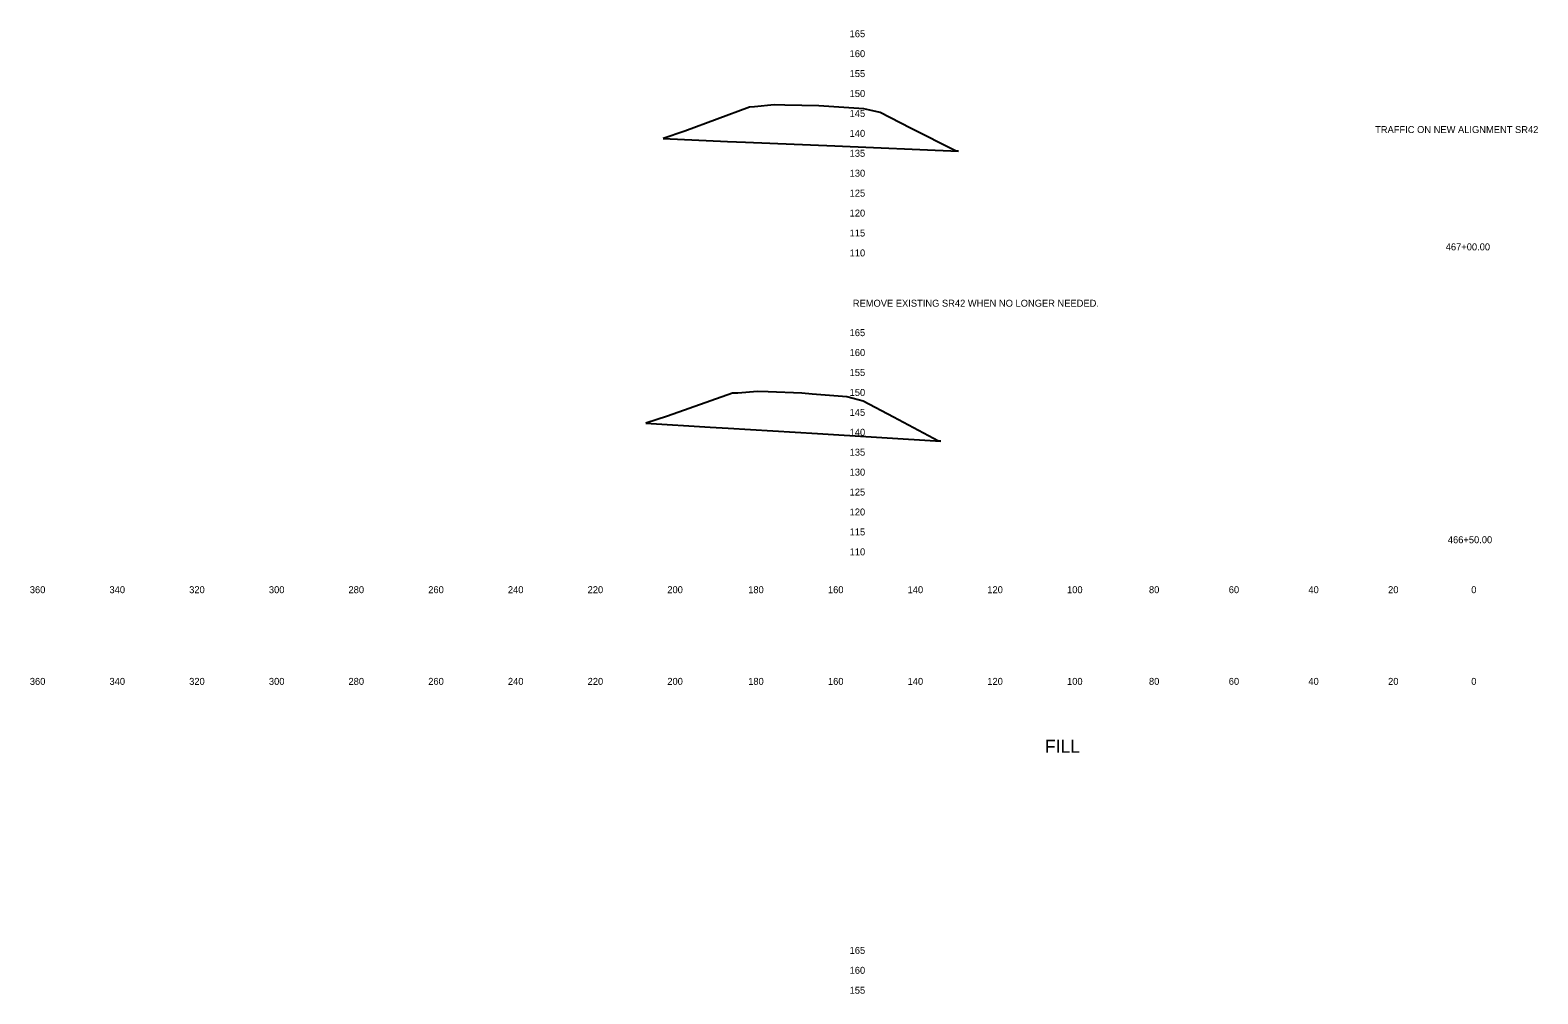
# Model space of a CAD drawing. Extents: x 21281 to 22024, y 6472 to 15208.
# Drawn here: x 21280.5 to 21658.8, y 8904.8 to 9146.6 of the extents above; entities that cross this region are included whole.
import ezdxf

# ---------------------------------------------------------------- set-up
doc = ezdxf.new("R2010")
doc.units = 0
for name, color, linetype in [('XS_SHEET_LABELS_ELEVATION', 7, 'Continuous'), ('XS_SHEET_LABELS_OFFSET', 7, 'Continuous'), ('XS_SHEET_LABELS_STATION', 7, 'Continuous'), ('XS_X_EXCESS', 7, 'Continuous')]:
    doc.layers.add(name, color=color, linetype=linetype)

msp = doc.modelspace()

# ---------------------------------------------------------------- linework, layer by layer
at = {"layer": 'XS_X_EXCESS'}
for p, q in [((21513.48, 9116.21), (21512.91, 9116.27)), ((21509.05, 9043.45), (21508.48, 9043.52))]:
    msp.add_line(p, q, dxfattribs=at)
for points in [[(21512.91, 9116.27), (21501.45, 9122.04), (21493.79, 9125.91), (21491.23, 9126.52), (21489.71, 9126.91), (21480.95, 9127.48), (21478.39, 9127.66), (21469.88, 9127.81), (21467.25, 9127.86), (21462.29, 9127.38), (21460.99, 9127.32), (21444.79, 9121.29), (21439.37, 9119.4)], [(21439.37, 9119.4), (21455.53, 9118.71), (21460.02, 9118.52), (21482.44, 9117.56), (21513.48, 9116.21)], [(21508.48, 9043.52), (21497.13, 9049.5), (21489.54, 9053.5), (21486.99, 9054.16), (21485.48, 9054.58), (21476.74, 9055.31), (21474.18, 9055.54), (21465.67, 9055.84), (21463.04, 9055.94), (21458.08, 9055.55), (21456.77, 9055.52), (21440.47, 9049.79), (21435.01, 9048)], [(21435.01, 9048), (21451.16, 9047.01), (21455.65, 9046.73), (21478.04, 9045.37), (21509.05, 9043.45)]]:
    msp.add_lwpolyline(points, dxfattribs=at)

# ---------------------------------------------------------------- texts
at = {"layer": 'XS_SHEET_LABELS_ELEVATION'}
for s, p in [('  165  ', (21484.84, 9144.84)), ('  160  ', (21484.84, 9139.84)), ('  155  ', (21484.84, 9134.84)), ('  150  ', (21484.84, 9129.84)), ('  145  ', (21484.84, 9124.84)), ('  140  ', (21484.84, 9119.84)), ('  135  ', (21484.84, 9114.84)), ('  130  ', (21484.84, 9109.84)), ('  125  ', (21484.84, 9104.84)), ('  120  ', (21484.84, 9099.84)), ('  115  ', (21484.84, 9094.84)), ('  110  ', (21484.84, 9089.84)), ('  165  ', (21484.84, 9069.84)), ('  160  ', (21484.84, 9064.84)), ('  155  ', (21484.84, 9059.84)), ('  150  ', (21484.84, 9054.84)), ('  145  ', (21484.84, 9049.84)), ('  140  ', (21484.84, 9044.84)), ('  135  ', (21484.84, 9039.84)), ('  130  ', (21484.84, 9034.84)), ('  125  ', (21484.84, 9029.84)), ('  120  ', (21484.84, 9024.84)), ('  115  ', (21484.84, 9019.84)), ('  110  ', (21484.84, 9014.84)), ('  165  ', (21484.84, 8914.84)), ('  160  ', (21484.84, 8909.84)), ('  155  ', (21484.84, 8904.84))]:
    msp.add_text(s, height=1.75, dxfattribs=at).set_placement(p)
at = {"layer": 'XS_SHEET_LABELS_OFFSET'}
for s, height, p in [('  360  ', 1.75, (21279.14, 9005.34)), ('  340  ', 1.75, (21299.13, 9005.34)), ('  320  ', 1.75, (21319.13, 9005.34)), ('  300  ', 1.75, (21339.13, 9005.34)), ('  280  ', 1.75, (21359.1, 9005.34)), ('  260  ', 1.75, (21379.11, 9005.34)), ('  240  ', 1.75, (21399.1, 9005.34)), ('  220  ', 1.75, (21419.1, 9005.34)), ('  200  ', 1.75, (21439.1, 9005.34)), ('  180  ', 1.75, (21459.39, 9005.34)), ('  160  ', 1.75, (21479.4, 9005.34)), ('  140  ', 1.75, (21499.39, 9005.34)), ('  120  ', 1.75, (21519.39, 9005.34)), ('  100  ', 1.75, (21539.39, 9005.34)), ('  80  ', 1.75, (21559.95, 9005.34)), ('  60  ', 1.75, (21579.97, 9005.34)), ('  40  ', 1.75, (21599.95, 9005.34)), ('  20  ', 1.75, (21619.95, 9005.34)), ('  0  ', 1.75, (21640.81, 9005.34)), ('  0  ', 1.75, (21640.81, 9005.34)), ('  360  ', 1.75, (21279.14, 8982.34)), ('  340  ', 1.75, (21299.13, 8982.34)), ('  320  ', 1.75, (21319.13, 8982.34)), ('  300  ', 1.75, (21339.13, 8982.34)), ('  280  ', 1.75, (21359.1, 8982.34)), ('  260  ', 1.75, (21379.11, 8982.34)), ('  240  ', 1.75, (21399.1, 8982.34)), ('  220  ', 1.75, (21419.1, 8982.34)), ('  200  ', 1.75, (21439.1, 8982.34)), ('  180  ', 1.75, (21459.39, 8982.34)), ('  160  ', 1.75, (21479.4, 8982.34)), ('  140  ', 1.75, (21499.39, 8982.34)), ('  120  ', 1.75, (21519.39, 8982.34)), ('  100  ', 1.75, (21539.39, 8982.34)), ('  80  ', 1.75, (21559.95, 8982.34)), ('  60  ', 1.75, (21579.97, 8982.34)), ('  40  ', 1.75, (21599.95, 8982.34)), ('  20  ', 1.75, (21619.95, 8982.34)), ('  0  ', 1.75, (21640.81, 8982.34)), ('  0  ', 1.75, (21640.81, 8982.34)), ('FILL', 3.273, (21535.18, 8965.29))]:
    msp.add_text(s, height=height, dxfattribs=at).set_placement(p)
at = {"layer": 'XS_SHEET_LABELS_STATION'}
for s, p in [('TRAFFIC ON NEW ALIGNMENT SR42', (21617.99, 9120.79)), ('  467+00.00  ', (21634.41, 9091.36)), ('REMOVE EXISTING SR42 WHEN NO LONGER NEEDED.', (21486.94, 9077.22)), ('  466+50.00  ', (21634.94, 9017.88))]:
    msp.add_text(s, height=1.75, dxfattribs=at).set_placement(p)

doc.saveas('drawing.dxf')
